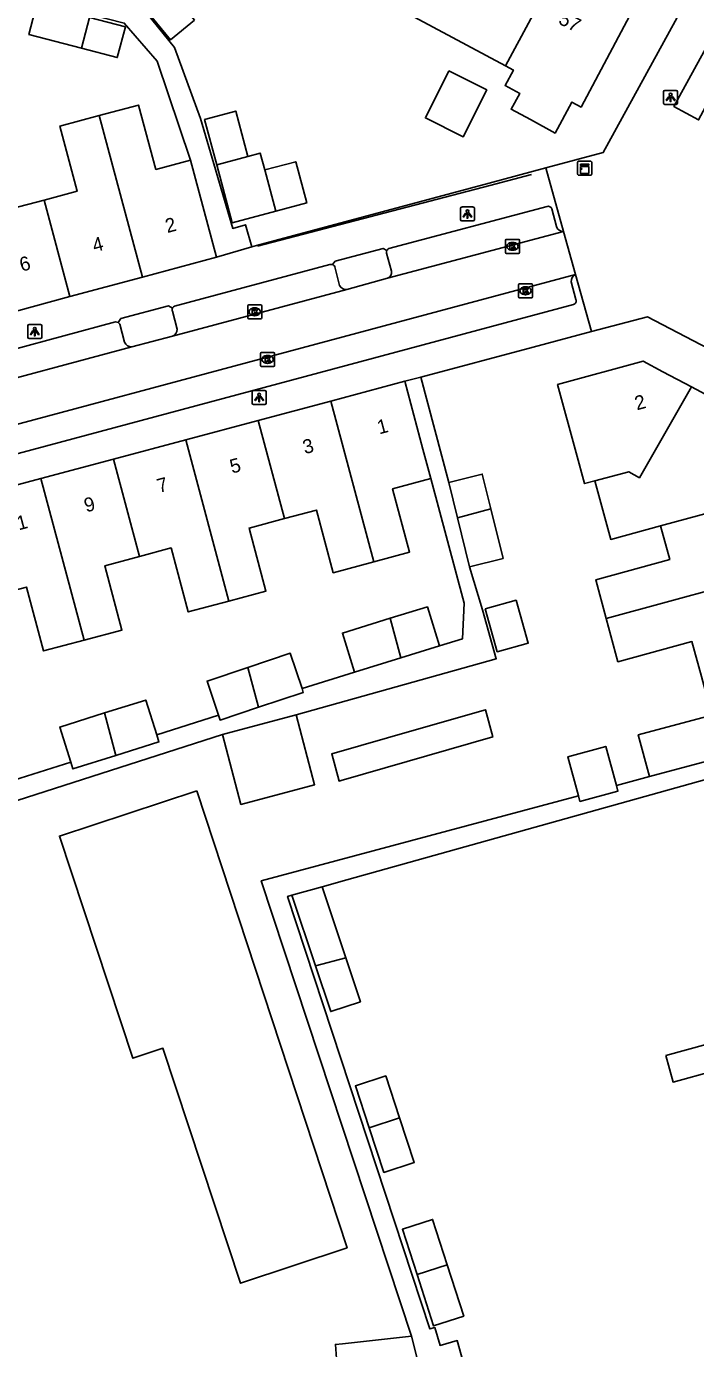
# Model space of a CAD drawing. Extents: x 159265 to 160143, y 383413 to 384319.
# Drawn here: x 159733 to 159780.7, y 383892.3 to 383986.4 of the extents above; entities that cross this region are included whole.
import ezdxf

# ---------------------------------------------------------------- set-up
doc = ezdxf.new("R2010")
doc.units = 0
for name, color, linetype in [('IMGEO_Fietspad_gesloten', 7, 'Continuous'), ('IMGEO_Kast', 7, 'Continuous'), ('IMGEO_Kolk', 7, 'Continuous'), ('IMGEO_Lichtpunt', 7, 'Continuous'), ('IMGEO_Muur', 7, 'Continuous'), ('IMGEO_Pand', 7, 'Continuous'), ('IMGEO_Pand_nummerreeks', 7, 'Continuous'), ('IMGEO_Parkeervlak_open', 7, 'Continuous'), ('IMGEO_Rijbaan_lokaal_open', 7, 'Continuous'), ('IMGEO_Voetpad_open', 7, 'Continuous')]:
    doc.layers.add(name, color=color, linetype=linetype)

msp = doc.modelspace()

# ---------------------------------------------------------------- linework, layer by layer
at = {"layer": 'IMGEO_Fietspad_gesloten'}
msp.add_lwpolyline([(159784.475, 383986.467), (159780.906, 383979.79), (159779.155, 383980.75), (159782.751, 383987.322)], dxfattribs=at)
at = {"layer": 'IMGEO_Kast'}
for p, q in [((159772.297, 383975.926), (159772.297, 383976.767)), ((159772.297, 383976.767), (159772.297, 383975.926)), ((159772.372, 383976.851), (159773.213, 383976.851)), ((159773.213, 383976.851), (159772.372, 383976.851)), ((159773.297, 383976.776), (159773.297, 383975.935)), ((159773.297, 383975.935), (159773.297, 383976.776)), ((159773.222, 383975.851), (159772.381, 383975.851)), ((159772.381, 383975.851), (159773.222, 383975.851))]:
    msp.add_line(p, q, dxfattribs=at)
for points in [[(159772.492, 383976.641), (159773.092, 383976.641), (159773.092, 383976.556), (159772.492, 383976.556), (159772.492, 383976.641)], [(159772.492, 383976.466), (159773.092, 383976.466), (159773.092, 383975.977), (159772.492, 383975.977), (159772.492, 383976.466)]]:
    msp.add_lwpolyline(points, dxfattribs=at)
msp.add_circle((159772.576, 383976.315), 0.0377, dxfattribs=at)
for centre, start, end in [((159772.375, 383976.773), 92.4484, 184.28452), ((159772.375, 383976.773), 92.4484, 184.28452), ((159773.219, 383976.773), 2.4484, 94.28452), ((159773.219, 383976.773), 2.4484, 94.28452), ((159772.375, 383975.929), 182.4484, 274.28452), ((159772.375, 383975.929), 182.4484, 274.28452), ((159773.219, 383975.929), 272.4484, 4.28452), ((159773.219, 383975.929), 272.4484, 4.28452)]:
    msp.add_arc(centre, 0.0779, start, end, dxfattribs=at)
at = {"layer": 'IMGEO_Kolk'}
for p, q in [((159767.155, 383970.358), (159767.155, 383971.21)), ((159767.23, 383971.284), (159768.082, 383971.284)), ((159767.643, 383971.064), (159767.668, 383971.064)), ((159768.156, 383971.21), (159768.156, 383970.358)), ((159768.082, 383970.284), (159767.23, 383970.284)), ((159767.666, 383970.504), (159767.641, 383970.504)), ((159768.085, 383967.196), (159768.085, 383968.048)), ((159768.16, 383968.122), (159769.012, 383968.122)), ((159768.573, 383967.902), (159768.598, 383967.902)), ((159769.086, 383968.048), (159769.086, 383967.196)), ((159769.012, 383967.122), (159768.16, 383967.122)), ((159768.596, 383967.342), (159768.571, 383967.342)), ((159748.801, 383965.7), (159748.801, 383966.552)), ((159748.876, 383966.626), (159749.728, 383966.626)), ((159749.289, 383966.406), (159749.314, 383966.406)), ((159749.802, 383966.552), (159749.802, 383965.7)), ((159749.728, 383965.626), (159748.876, 383965.626)), ((159749.312, 383965.846), (159749.287, 383965.846)), ((159749.72, 383962.305), (159749.72, 383963.157)), ((159749.795, 383963.231), (159750.647, 383963.231)), ((159750.721, 383963.157), (159750.721, 383962.305)), ((159750.647, 383962.231), (159749.795, 383962.231)), ((159750.231, 383962.451), (159750.206, 383962.451)), ((159750.208, 383963.011), (159750.233, 383963.011))]:
    msp.add_line(p, q, dxfattribs=at)
for points in [[(159767.155, 383970.358), (159767.155, 383971.21)], [(159767.23, 383971.284), (159768.082, 383971.284)], [(159767.476, 383970.984), (159767.599, 383970.984), (159767.599, 383970.833), (159767.729, 383970.984), (159767.893, 383970.984), (159767.747, 383970.833), (159767.9, 383970.584), (159767.748, 383970.584), (159767.663, 383970.748), (159767.599, 383970.681), (159767.599, 383970.584), (159767.476, 383970.584), (159767.476, 383970.984)], [(159768.156, 383971.21), (159768.156, 383970.358)], [(159768.082, 383970.284), (159767.23, 383970.284)], [(159768.085, 383967.196), (159768.085, 383968.048)], [(159768.16, 383968.122), (159769.012, 383968.122)], [(159768.406, 383967.822), (159768.529, 383967.822), (159768.529, 383967.671), (159768.659, 383967.822), (159768.823, 383967.822), (159768.677, 383967.671), (159768.83, 383967.422), (159768.678, 383967.422), (159768.593, 383967.586), (159768.529, 383967.519), (159768.529, 383967.422), (159768.406, 383967.422), (159768.406, 383967.822)], [(159769.086, 383968.048), (159769.086, 383967.196)], [(159769.012, 383967.122), (159768.16, 383967.122)], [(159748.801, 383965.7), (159748.801, 383966.552)], [(159748.876, 383966.626), (159749.728, 383966.626)], [(159749.122, 383966.326), (159749.245, 383966.326), (159749.245, 383966.175), (159749.375, 383966.326), (159749.539, 383966.326), (159749.393, 383966.175), (159749.546, 383965.926), (159749.394, 383965.926), (159749.309, 383966.09), (159749.245, 383966.023), (159749.245, 383965.926), (159749.122, 383965.926), (159749.122, 383966.326)], [(159749.802, 383966.552), (159749.802, 383965.7)], [(159749.728, 383965.626), (159748.876, 383965.626)], [(159749.72, 383962.305), (159749.72, 383963.157)], [(159749.795, 383963.231), (159750.647, 383963.231)], [(159750.721, 383963.157), (159750.721, 383962.305)], [(159750.647, 383962.231), (159749.795, 383962.231)], [(159750.041, 383962.931), (159750.164, 383962.931), (159750.164, 383962.78), (159750.294, 383962.931), (159750.458, 383962.931), (159750.312, 383962.78), (159750.465, 383962.531), (159750.313, 383962.531), (159750.228, 383962.695), (159750.164, 383962.628), (159750.164, 383962.531), (159750.041, 383962.531), (159750.041, 383962.931)]]:
    msp.add_lwpolyline(points, dxfattribs=at)
for centre, start, end in [((159767.232, 383971.208), 91.55205, 178.44795), ((159767.232, 383971.208), 91.55205, 178.44795), ((159768.08, 383971.208), 1.55205, 88.44795), ((159768.08, 383971.208), 1.55205, 88.44795), ((159767.232, 383970.36), 181.55205, 268.44795), ((159767.232, 383970.36), 181.55205, 268.44795), ((159768.08, 383970.36), 271.55205, 358.44795), ((159768.08, 383970.36), 271.55205, 358.44795), ((159768.162, 383968.046), 91.55205, 178.44795), ((159768.162, 383968.046), 91.55205, 178.44795), ((159769.01, 383968.046), 1.55205, 88.44795), ((159769.01, 383968.046), 1.55205, 88.44795), ((159768.162, 383967.198), 181.55205, 268.44795), ((159768.162, 383967.198), 181.55205, 268.44795), ((159769.01, 383967.198), 271.55205, 358.44795), ((159769.01, 383967.198), 271.55205, 358.44795), ((159748.878, 383966.55), 91.55205, 178.44795), ((159748.878, 383966.55), 91.55205, 178.44795), ((159749.726, 383966.55), 1.55205, 88.44795), ((159749.726, 383966.55), 1.55205, 88.44795), ((159748.878, 383965.702), 181.55205, 268.44795), ((159748.878, 383965.702), 181.55205, 268.44795), ((159749.726, 383965.702), 271.55205, 358.44795), ((159749.726, 383965.702), 271.55205, 358.44795), ((159749.797, 383963.155), 91.55205, 178.44795), ((159749.797, 383963.155), 91.55205, 178.44795), ((159750.645, 383963.155), 1.55205, 88.44795), ((159750.645, 383963.155), 1.55205, 88.44795), ((159749.797, 383962.307), 181.55205, 268.44795), ((159749.797, 383962.307), 181.55205, 268.44795), ((159750.645, 383962.307), 271.55205, 358.44795), ((159750.645, 383962.307), 271.55205, 358.44795)]:
    msp.add_arc(centre, 0.0765, start, end, dxfattribs=at)
for centre, major_axis, ratio, start_param, end_param in [((159767.642, 383970.784), (-0.387, 0.002), 0.722429, 4.712389, 7.853982), ((159767.667, 383970.784), (-0.39, 0.002), 0.717154, 1.570796, 4.712389), ((159768.572, 383967.622), (-0.387, 0.002), 0.722429, 4.712389, 7.853982), ((159768.597, 383967.622), (-0.39, 0.002), 0.717154, 1.570796, 4.712389), ((159749.288, 383966.126), (-0.387, 0.002), 0.722429, 4.712389, 7.853982), ((159749.313, 383966.126), (-0.39, 0.002), 0.717154, 1.570796, 4.712389), ((159750.207, 383962.731), (-0.387, 0.002), 0.722429, 4.712389, 7.853982), ((159750.232, 383962.731), (-0.39, 0.002), 0.717154, 1.570796, 4.712389)]:
    msp.add_ellipse(centre, major_axis=major_axis, ratio=ratio, start_param=start_param, end_param=end_param, dxfattribs=at)
at = {"layer": 'IMGEO_Lichtpunt'}
for p, q in [((159778.418, 383981.8), (159778.418, 383980.993)), ((159778.418, 383981.8), (159778.418, 383980.993)), ((159779.32, 383981.895), (159778.512, 383981.895)), ((159779.32, 383981.895), (159778.512, 383981.895)), ((159779.414, 383980.993), (159779.414, 383981.8)), ((159779.414, 383980.993), (159779.414, 383981.8)), ((159778.512, 383980.899), (159779.32, 383980.899)), ((159778.512, 383980.899), (159779.32, 383980.899)), ((159763.948, 383973.493), (159763.948, 383972.686)), ((159763.948, 383973.493), (159763.948, 383972.686)), ((159764.85, 383973.588), (159764.042, 383973.588)), ((159764.85, 383973.588), (159764.042, 383973.588)), ((159764.944, 383972.686), (159764.944, 383973.493)), ((159764.944, 383972.686), (159764.944, 383973.493)), ((159764.042, 383972.592), (159764.85, 383972.592)), ((159764.042, 383972.592), (159764.85, 383972.592)), ((159733.139, 383965.116), (159733.139, 383964.309)), ((159733.139, 383965.116), (159733.139, 383964.309)), ((159734.041, 383965.211), (159733.233, 383965.211)), ((159734.041, 383965.211), (159733.233, 383965.211)), ((159734.135, 383964.309), (159734.135, 383965.116)), ((159734.135, 383964.309), (159734.135, 383965.116)), ((159733.233, 383964.215), (159734.041, 383964.215)), ((159733.233, 383964.215), (159734.041, 383964.215)), ((159749.123, 383960.422), (159749.123, 383959.615)), ((159749.123, 383960.422), (159749.123, 383959.615)), ((159750.025, 383960.517), (159749.217, 383960.517)), ((159750.025, 383960.517), (159749.217, 383960.517)), ((159750.119, 383959.615), (159750.119, 383960.422)), ((159750.119, 383959.615), (159750.119, 383960.422)), ((159749.217, 383959.521), (159750.025, 383959.521)), ((159749.217, 383959.521), (159750.025, 383959.521))]:
    msp.add_line(p, q, dxfattribs=at)
for points in [[(159778.792, 383981.464), (159778.831, 383981.436), (159778.643, 383981.174), (159778.605, 383981.201), (159778.792, 383981.464)], [(159778.894, 383981.416), (159778.941, 383981.416), (159778.941, 383981.094), (159778.894, 383981.094), (159778.894, 383981.416)], [(159779.004, 383981.436), (159779.042, 383981.463), (159779.229, 383981.201), (159779.19, 383981.173), (159779.004, 383981.436)], [(159764.322, 383973.157), (159764.361, 383973.129), (159764.173, 383972.867), (159764.135, 383972.894), (159764.322, 383973.157)], [(159764.424, 383973.109), (159764.471, 383973.109), (159764.471, 383972.787), (159764.424, 383972.787), (159764.424, 383973.109)], [(159764.534, 383973.129), (159764.572, 383973.156), (159764.759, 383972.894), (159764.72, 383972.866), (159764.534, 383973.129)], [(159733.513, 383964.78), (159733.552, 383964.752), (159733.364, 383964.49), (159733.326, 383964.517), (159733.513, 383964.78)], [(159733.615, 383964.732), (159733.662, 383964.732), (159733.662, 383964.41), (159733.615, 383964.41), (159733.615, 383964.732)], [(159733.725, 383964.752), (159733.763, 383964.779), (159733.95, 383964.517), (159733.911, 383964.489), (159733.725, 383964.752)], [(159749.497, 383960.086), (159749.536, 383960.058), (159749.348, 383959.796), (159749.31, 383959.823), (159749.497, 383960.086)], [(159749.599, 383960.038), (159749.646, 383960.038), (159749.646, 383959.716), (159749.599, 383959.716), (159749.599, 383960.038)], [(159749.709, 383960.058), (159749.747, 383960.085), (159749.934, 383959.823), (159749.895, 383959.795), (159749.709, 383960.058)]]:
    msp.add_lwpolyline(points, dxfattribs=at)
for centre in [(159778.917, 383981.598), (159764.447, 383973.291), (159733.638, 383964.914), (159749.622, 383960.22)]:
    msp.add_circle(centre, 0.0994, dxfattribs=at)
for centre, start, end in [((159778.512, 383981.8), 90, 180), ((159778.512, 383981.8), 90, 180), ((159779.32, 383981.8), 0, 90), ((159779.32, 383981.8), 0, 90), ((159778.512, 383980.993), 180, 270), ((159778.512, 383980.993), 180, 270), ((159779.32, 383980.993), 270, 0), ((159779.32, 383980.993), 270, 360), ((159764.042, 383973.493), 90, 180), ((159764.042, 383973.493), 90, 180), ((159764.85, 383973.493), 0, 90), ((159764.85, 383973.493), 0, 90), ((159764.042, 383972.686), 180, 270), ((159764.042, 383972.686), 180, 270), ((159764.85, 383972.686), 270, 0), ((159764.85, 383972.686), 270, 360), ((159733.233, 383965.116), 90, 180), ((159733.233, 383965.116), 90, 180), ((159734.041, 383965.116), 0, 90), ((159734.041, 383965.116), 0, 90), ((159733.233, 383964.309), 180, 270), ((159733.233, 383964.309), 180, 270), ((159734.041, 383964.309), 270, 0), ((159734.041, 383964.309), 270, 360), ((159749.217, 383960.422), 90, 180), ((159749.217, 383960.422), 90, 180), ((159750.025, 383960.422), 0, 90), ((159750.025, 383960.422), 0, 90), ((159749.217, 383959.615), 180, 270), ((159749.217, 383959.615), 180, 270), ((159750.025, 383959.615), 270, 0), ((159750.025, 383959.615), 270, 360)]:
    msp.add_arc(centre, 0.0946, start, end, dxfattribs=at)
at = {"layer": 'IMGEO_Muur'}
for points in [[(159769.01, 383975.903), (159766.036, 383975.127)], [(159766.036, 383975.127), (159749.489, 383970.809)]]:
    msp.add_lwpolyline(points, dxfattribs=at)
at = {"layer": 'IMGEO_Pand'}
for points in [[(159767.17, 383983.641), (159760.631, 383987.137), (159761.773, 383989.273), (159763.233, 383991.981), (159764.196, 383993.733), (159767.732, 383991.79), (159767.838, 383991.982), (159770.767, 383990.366)], [(159770.767, 383990.366), (159772.596, 383989.357), (159772.497, 383989.167), (159776.022, 383987.218), (159772.54, 383980.708), (159771.885, 383981.058), (159770.694, 383978.858), (159768.935, 383979.811), (159767.561, 383980.545), (159768.169, 383981.683), (159767.13, 383982.239), (159767.722, 383983.346), (159767.17, 383983.641)], [(159767.17, 383983.641), (159770.767, 383990.366)], [(159745.013, 383986.9), (159743.305, 383985.495), (159741.321, 383987.907), (159743.029, 383989.312), (159745.013, 383986.9)], [(159737.541, 383987.088), (159733.796, 383988.062), (159733.224, 383985.866), (159736.97, 383984.891)], [(159737.541, 383987.088), (159736.97, 383984.891)], [(159736.97, 383984.891), (159739.518, 383984.228), (159740.089, 383986.424), (159737.541, 383987.088)], [(159763.125, 383983.279), (159765.825, 383981.929), (159764.153, 383978.586), (159761.454, 383979.935), (159763.125, 383983.279)], [(159734.299, 383974.083), (159736.665, 383974.715), (159735.427, 383979.348), (159738.232, 383980.098)], [(159738.232, 383980.098), (159741.037, 383980.847), (159742.263, 383976.259), (159744.733, 383976.92)], [(159741.307, 383968.589), (159738.232, 383980.098)], [(159746.597, 383976.598), (159745.734, 383979.821), (159747.947, 383980.415), (159748.812, 383977.192)], [(159727.924, 383977.348), (159730.695, 383978.088), (159731.933, 383973.451), (159734.299, 383974.083)], [(159748.812, 383977.192), (159749.698, 383977.43), (159750.021, 383976.225)], [(159746.583, 383970.005), (159744.733, 383976.92)], [(159748.812, 383977.192), (159746.597, 383976.598)], [(159750.808, 383973.292), (159747.704, 383972.459), (159746.597, 383976.598)], [(159750.021, 383976.225), (159752.219, 383976.814), (159753.003, 383973.881), (159750.808, 383973.292)], [(159750.021, 383976.225), (159750.808, 383973.292)], [(159736.137, 383967.201), (159734.299, 383974.083)], [(159746.583, 383970.005), (159741.307, 383968.589)], [(159741.307, 383968.589), (159736.137, 383967.201)], [(159736.137, 383967.201), (159731.004, 383965.823)], [(159780.397, 383960.772), (159778.37, 383961.852), (159776.953, 383962.607), (159770.863, 383960.946), (159772.201, 383956.071), (159772.793, 383953.883), (159773.526, 383954.081)], [(159754.715, 383959.761), (159759.99, 383961.172)], [(159759.99, 383961.172), (159761.28, 383956.348), (159761.84, 383954.251)], [(159773.526, 383954.081), (159775.94, 383954.733), (159776.693, 383954.302), (159780.397, 383960.772)], [(159780.397, 383960.772), (159782.041, 383959.896), (159783.841, 383958.937), (159784.395, 383956.892), (159785.492, 383952.847)], [(159749.555, 383958.381), (159754.715, 383959.761)], [(159757.775, 383948.307), (159754.715, 383959.761)], [(159744.397, 383957.001), (159749.555, 383958.381)], [(159749.555, 383958.381), (159751.425, 383951.389)], [(159739.238, 383955.621), (159744.397, 383957.001)], [(159744.397, 383957.001), (159747.465, 383945.521)], [(159734.08, 383954.241), (159739.238, 383955.621)], [(159739.238, 383955.621), (159741.088, 383948.697)], [(159728.92, 383952.86), (159734.08, 383954.241)], [(159737.154, 383942.734), (159734.08, 383954.241)], [(159761.84, 383954.251), (159759.117, 383953.523), (159760.329, 383948.989), (159757.775, 383948.307)], [(159763.12, 383953.973), (159765.503, 383954.561), (159766.116, 383952.08)], [(159763.745, 383951.44), (159763.12, 383953.973)], [(159778.206, 383950.875), (159774.652, 383949.913), (159773.526, 383954.081)], [(159778.206, 383950.875), (159785.492, 383952.847)], [(159757.775, 383948.307), (159754.898, 383947.538), (159753.707, 383951.999), (159751.425, 383951.389)], [(159766.116, 383952.08), (159763.745, 383951.44)], [(159766.116, 383952.08), (159766.986, 383948.553), (159764.602, 383947.965)], [(159751.425, 383951.389), (159748.902, 383950.715), (159750.102, 383946.226), (159747.465, 383945.521)], [(159764.602, 383947.965), (159763.745, 383951.44)], [(159774.329, 383944.283), (159773.582, 383947.039), (159778.857, 383948.47), (159778.206, 383950.875)], [(159747.465, 383945.521), (159744.57, 383944.747), (159743.352, 383949.302), (159741.088, 383948.697)], [(159741.088, 383948.697), (159738.618, 383948.037), (159739.843, 383943.453), (159737.154, 383942.734)], [(159786.89, 383947.688), (159774.329, 383944.283)], [(159737.154, 383942.734), (159734.265, 383941.962), (159733.048, 383946.516), (159730.777, 383945.91)], [(159765.715, 383944.958), (159766.574, 383941.908), (159768.777, 383942.528), (159767.918, 383945.579), (159765.715, 383944.958)], [(159756.402, 383940.461), (159755.547, 383943.241), (159758.946, 383944.287)], [(159758.946, 383944.287), (159761.603, 383945.104), (159762.458, 383942.324)], [(159759.695, 383941.474), (159758.946, 383944.287)], [(159781.109, 383940.153), (159780.437, 383942.628), (159775.167, 383941.197), (159774.329, 383944.283)], [(159748.812, 383940.792), (159751.83, 383941.798), (159752.671, 383939.277)], [(159759.695, 383941.474), (159756.402, 383940.461)], [(159762.458, 383942.324), (159759.695, 383941.474)], [(159746.717, 383937.387), (159745.906, 383939.823), (159748.812, 383940.792)], [(159748.812, 383940.792), (159749.569, 383937.949)], [(159777.417, 383933.011), (159776.612, 383935.978), (159781.851, 383937.399), (159781.109, 383940.153)], [(159749.569, 383937.949), (159752.759, 383939.012), (159752.671, 383939.277)], [(159738.611, 383937.545), (159741.548, 383938.464), (159742.323, 383935.992)], [(159746.717, 383937.387), (159746.784, 383937.187), (159746.834, 383937.037), (159749.569, 383937.949)], [(159755.446, 383932.726), (159766.251, 383935.834), (159765.726, 383937.771), (159760.832, 383936.364), (159754.786, 383934.625), (159755.311, 383932.688), (159755.446, 383932.726)], [(159736.201, 383934.049), (159735.419, 383936.545), (159738.611, 383937.545)], [(159738.611, 383937.545), (159739.416, 383934.523)], [(159752.247, 383937.414), (159753.57, 383932.427), (159748.324, 383931.035), (159747.001, 383936.022)], [(159747.001, 383936.022), (159752.247, 383937.414)], [(159739.416, 383934.523), (159742.482, 383935.483), (159742.323, 383935.992)], [(159789.947, 383936.408), (159785.094, 383935.077), (159782.657, 383934.418), (159777.417, 383933.011)], [(159772.346, 383931.649), (159771.595, 383934.433), (159774.302, 383935.163), (159775.054, 383932.376)], [(159736.201, 383934.049), (159736.353, 383933.564), (159739.416, 383934.523)], [(159775.054, 383932.376), (159775.161, 383931.978), (159772.454, 383931.248), (159772.346, 383931.649)], [(159745.172, 383932.01), (159735.399, 383928.777), (159740.633, 383912.954), (159742.77, 383913.661), (159748.301, 383896.926), (159755.881, 383899.453), (159745.172, 383932.01)], [(159751.951, 383924.568), (159754.103, 383925.163)], [(159753.631, 383919.527), (159751.951, 383924.568)], [(159754.103, 383925.163), (159755.786, 383920.114)], [(159755.786, 383920.114), (159756.833, 383916.975), (159754.718, 383916.269), (159753.631, 383919.527)], [(159753.631, 383919.527), (159755.786, 383920.114)], [(159778.58, 383913.152), (159781.514, 383913.943), (159782.027, 383912.043), (159779.093, 383911.251), (159778.58, 383913.152)], [(159757.457, 383908.004), (159756.477, 383910.983), (159758.631, 383911.692), (159759.611, 383908.713)], [(159759.611, 383908.713), (159760.658, 383905.53), (159758.504, 383904.821), (159757.457, 383908.004)], [(159757.457, 383908.004), (159759.611, 383908.713)], [(159760.86, 383897.541), (159759.818, 383900.775), (159761.97, 383901.468), (159763.012, 383898.235)], [(159763.012, 383898.235), (159764.19, 383894.581), (159762.038, 383893.887), (159760.86, 383897.541)], [(159760.86, 383897.541), (159763.012, 383898.235)], [(159760.457, 383893.145), (159755.563, 383892.604), (159755.048, 383892.566), (159755.241, 383889.909), (159757.396, 383890.077), (159760.479, 383878.009), (159764.1, 383878.938)], [(159760.457, 383893.145), (159762.064, 383886.88), (159764.1, 383878.938)]]:
    msp.add_lwpolyline(points, dxfattribs=at)
at = {"layer": 'IMGEO_Parkeervlak_open'}
for points in [[(159758.692, 383970.289), (159759.033, 383969.008)], [(159755.342, 383968.003), (159754.999, 383969.337)], [(159743.451, 383966.168), (159743.771, 383964.881)], [(159740.04, 383963.967), (159739.708, 383965.231)]]:
    msp.add_lwpolyline(points, dxfattribs=at)
for centre, radius, start, end in [((159758.96, 383970.367), 0.279, 153.57016, 196.24561), ((159754.747, 383969.225), 0.276, 23.87429, 70.22985), ((159758.601, 383968.917), 0.441, 291.93075, 11.86481), ((159755.828, 383968.246), 0.543, 206.54269, 272.72203), ((159743.672, 383966.281), 0.248, 153.00805, 206.99195), ((159739.397, 383965.013), 0.38, 35.0523, 62.2136), ((159743.27, 383964.854), 0.502, 290.03171, 3.0674), ((159740.491, 383964.103), 0.471, 196.75295, 276.8109)]:
    msp.add_arc(centre, radius, start, end, dxfattribs=at)
at = {"layer": 'IMGEO_Rijbaan_lokaal_open'}
for points in [[(159758.766, 383968.508), (159771.293, 383971.845)], [(159771.293, 383971.845), (159772.148, 383968.784)], [(159708.238, 383951.642), (159772.148, 383968.784)], [(159755.854, 383967.703), (159758.766, 383968.508)], [(159743.442, 383964.383), (159755.854, 383967.703)], [(159743.442, 383964.383), (159740.547, 383963.635)], [(159740.547, 383963.635), (159728.168, 383960.313)]]:
    msp.add_lwpolyline(points, dxfattribs=at)
at = {"layer": 'IMGEO_Voetpad_open'}
for points in [[(159732.797, 384005.979), (159724.687, 383990.848), (159738.883, 383989.039), (159739.826, 383988.736), (159741.165, 383987.949), (159743.582, 383984.943), (159745.444, 383979.884), (159747.74, 383972.058), (159748.634, 383972.321), (159749.097, 383970.743)], [(159744.733, 383976.92), (159742.345, 383983.979), (159740.012, 383986.687), (159733.564, 383988.34), (159695.96, 383993.051), (159703.26, 383965.725)], [(159780.198, 383988.588), (159774.115, 383977.461), (159770.03, 383976.366)], [(159749.097, 383970.743), (159749.436, 383970.842), (159765.994, 383975.283), (159770.03, 383976.366)], [(159770.03, 383976.366), (159771.293, 383971.845)], [(159770.126, 383973.633), (159758.861, 383970.625)], [(159770.791, 383972.189), (159770.452, 383973.449)], [(159749.097, 383970.743), (159746.583, 383970.005)], [(159758.71, 383970.491), (159758.438, 383970.634), (159755.033, 383969.741), (159754.84, 383969.485)], [(159754.658, 383969.486), (159743.59, 383966.517)], [(159772.148, 383968.784), (159773.286, 383964.712)], [(159771.834, 383968.263), (159772.165, 383966.997)], [(159772, 383966.637), (159658.57, 383936.213)], [(159739.574, 383965.349), (159739.775, 383965.636), (159743.169, 383966.558), (159743.451, 383966.393)], [(159728.331, 383962.413), (159739.386, 383965.398)], [(159773.286, 383964.712), (159777.272, 383965.773), (159786.462, 383960.973), (159787.021, 383958.859)], [(159761.123, 383961.474), (159769.133, 383963.606), (159773.286, 383964.712)], [(159759.99, 383961.172), (159761.123, 383961.474)], [(159761.123, 383961.474), (159763.12, 383953.973)], [(159762.458, 383942.324), (159764.106, 383942.831), (159764.213, 383945.375), (159761.84, 383954.251)], [(159764.602, 383947.965), (159765.519, 383944.903), (159766.503, 383941.407), (159752.247, 383937.414)], [(159752.671, 383939.277), (159756.402, 383940.461)], [(159742.323, 383935.992), (159746.717, 383937.387)], [(159747.001, 383936.022), (159672.409, 383912.034)], [(159732.14, 383932.76), (159736.201, 383934.049)], [(159754.103, 383925.163), (159755.861, 383925.649), (159785.907, 383934.055)], [(159777.417, 383933.011), (159775.054, 383932.376)], [(159772.346, 383931.649), (159749.77, 383925.587), (159760.457, 383893.145)], [(159797.859, 383889.997), (159766.14, 383881.436), (159764.282, 383890.798), (159763.729, 383892.843), (159762.504, 383892.493), (159762.122, 383893.769), (159761.762, 383893.671), (159751.636, 383924.481), (159751.951, 383924.568)]]:
    msp.add_lwpolyline(points, dxfattribs=at)
for centre, radius, start, end in [((159770.195, 383973.375), 0.267, 16.12991, 104.98784), ((159771.251, 383972.323), 0.479, 196.18948, 274.96804), ((159758.959, 383970.362), 0.281, 110.5208, 152.65201), ((159754.748, 383969.226), 0.275, 70.35294, 109.01744), ((159772.371, 383968.295), 0.538, 114.4812, 183.36514), ((159771.917, 383966.893), 0.269, 288.03741, 22.71546), ((159743.681, 383966.275), 0.259, 110.62304, 152.84839), ((159739.381, 383964.995), 0.403, 61.4409, 89.34217)]:
    msp.add_arc(centre, radius, start, end, dxfattribs=at)

# ---------------------------------------------------------------- texts
at = {"layer": 'IMGEO_Pand_nummerreeks'}
for s, rotation, p in [('57', 332.38343, (159770.861, 383986.688)), ('2', 14.86253, (159743.077, 383971.728)), ('4', 14.86253, (159737.892, 383970.352)), ('6', 14.86253, (159732.704, 383968.975)), ('2', 15.12609, (159776.514, 383959.099)), ('1', 14.91409, (159758.17, 383957.387)), ('3', 14.91409, (159752.871, 383955.975)), ('5', 14.91409, (159747.681, 383954.592)), ('7', 14.91409, (159742.491, 383953.21)), ('9', 14.91409, (159737.302, 383951.828)), ('11', 14.91409, (159731.777, 383950.357))]:
    msp.add_text(s, height=1, rotation=rotation, dxfattribs=at).set_placement(p)

doc.saveas('drawing.dxf')
